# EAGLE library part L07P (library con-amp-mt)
AMP MT CONNECTOR
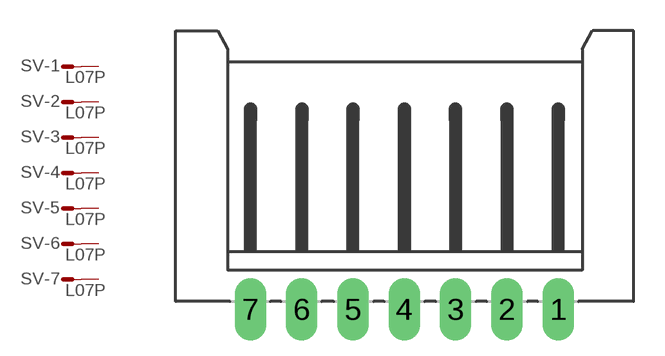
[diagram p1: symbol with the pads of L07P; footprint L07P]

Designator prefix SV; gates -1=M -2=M -3=M -4=M -5=M -6=M -7=M

## L07P (OC_FARNELL: unknown; OC_NEWARK: unknown)  [L07P]
1  -1:S  pas
2  -2:S  pas
3  -3:S  pas
4  -4:S  pas
5  -5:S  pas
6  -6:S  pas
7  -7:S  pas

## Footprint L07P (pad centres in mm)
AMP MT CONNECTOR
drill 1.016 long: 1 7.5,-6.25; 2 5,-6.25; 3 2.5,-6.25; 4 0,-6.25; 5 -2.5,-6.25; 6 -5,-6.25; 7 -7.5,-6.25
